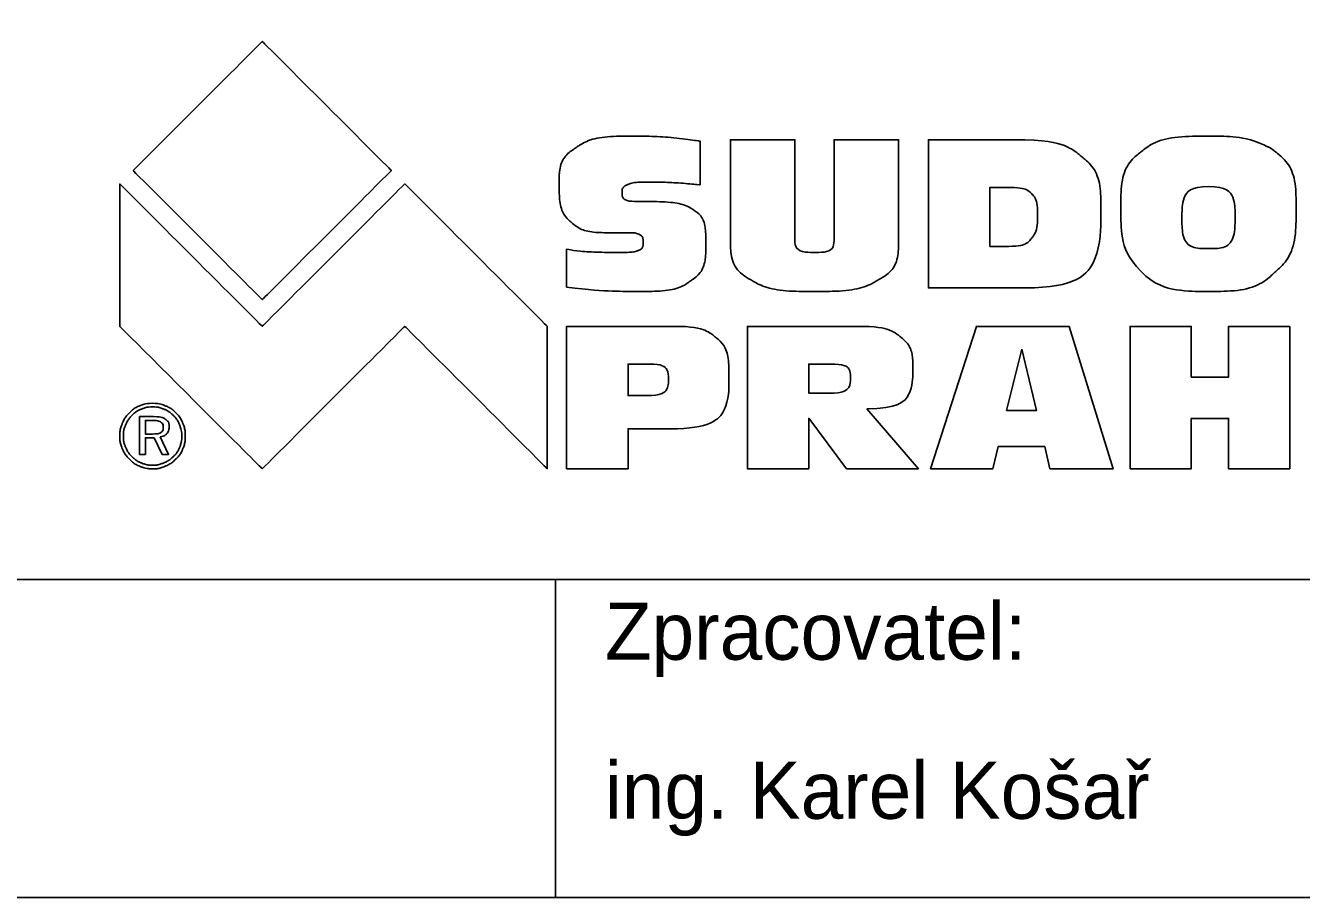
# Model space of a CAD drawing. Extents: x -311 to -101, y -2117 to -1820.
# Drawn here: x -172.5 to -130.4, y -2020.7 to -1991.91 of the extents above; entities that cross this region are included whole.
import ezdxf

# ---------------------------------------------------------------- set-up
doc = ezdxf.new("R2010")
doc.units = 0
for name, color, linetype in [('Rozpiska - logo SUDOP PRAHA', 7, 'Continuous'), ('Rozpiska_pole_6', 7, 'Continuous'), ('Rozpiska_pole_7', 7, 'Continuous')]:
    doc.layers.add(name, color=color, linetype=linetype)

msp = doc.modelspace()

# ---------------------------------------------------------------- linework, layer by layer
at = {"layer": 'Rozpiska - logo SUDOP PRAHA'}
for points in [[(-139.881, -1995.683), (-142.705, -1995.683), (-142.705, -2000.574), (-139.503, -2000.574)], [(-140.057, -1999.203), (-140.679, -1999.203), (-140.679, -1997.255), (-140.126, -1997.255)], [(-151.132, -2001.843), (-154.65, -2001.843), (-154.65, -2006.546), (-152.618, -2006.546), (-152.618, -2005.225), (-151.212, -2005.225)], [(-145.099, -2001.843), (-148.678, -2001.843), (-148.678, -2006.546), (-146.654, -2006.546), (-146.654, -2004.879), (-145.407, -2006.546), (-143.035, -2006.546), (-144.743, -2004.563)], [(-140.582, -2006.546), (-140.405, -2005.813), (-138.867, -2005.813), (-138.697, -2006.546), (-136.615, -2006.546), (-138.066, -2001.843), (-141.126, -2001.843), (-142.635, -2006.546), (-140.582, -2006.546)], [(-139.629, -2002.596), (-139.139, -2004.618), (-140.126, -2004.618), (-139.629, -2002.596)], [(-152.015, -2004.127), (-152.618, -2004.127), (-152.618, -2003.087), (-151.913, -2003.087)], [(-145.978, -2004.049), (-146.654, -2004.049), (-146.654, -2003.087), (-145.953, -2003.087)], [(-168.28, -2004.824), (-168.737, -2004.824), (-168.737, -2006.069), (-168.549, -2006.069), (-168.549, -2005.522), (-168.258, -2005.522), (-167.995, -2006.069), (-167.781, -2006.069), (-168.059, -2005.495)], [(-168.316, -2005.398), (-168.549, -2005.398), (-168.549, -2004.951), (-168.316, -2004.951)]]:
    msp.add_lwpolyline(points, dxfattribs=at)
for points in [[(-168.952, -1996.7), (-168.952, -1996.7), (-164.69, -1992.438), (-164.69, -1992.438), (-164.69, -1992.438), (-164.69, -1992.438), (-160.429, -1996.7), (-160.429, -1996.7), (-160.429, -1996.7), (-160.429, -1996.7), (-164.69, -2000.961), (-164.69, -2000.961), (-164.69, -2000.961), (-164.69, -2000.961), (-168.952, -1996.7), (-168.952, -1996.7)], [(-154.65, -2000.554), (-153.886, -2000.645), (-153.084, -2000.691), (-152.243, -2000.691), (-152.243, -2000.691), (-151.439, -2000.691), (-150.872, -2000.573), (-150.544, -2000.336), (-150.544, -2000.336), (-150.214, -2000.1), (-150.049, -1999.692), (-150.049, -1999.112), (-150.049, -1999.112), (-150.049, -1998.545), (-150.198, -1998.167), (-150.495, -1997.978), (-150.495, -1997.978), (-150.775, -1997.808), (-151.344, -1997.723), (-152.202, -1997.723), (-152.202, -1997.723), (-152.613, -1997.723), (-152.819, -1997.626), (-152.819, -1997.432), (-152.819, -1997.432), (-152.819, -1997.309), (-152.758, -1997.22), (-152.637, -1997.165), (-152.637, -1997.165), (-152.514, -1997.109), (-152.298, -1997.081), (-151.99, -1997.081), (-151.99, -1997.081), (-151.468, -1997.081), (-150.895, -1997.111), (-150.244, -1997.171), (-150.244, -1997.171), (-150.244, -1997.171), (-150.244, -1995.729), (-150.244, -1995.729), (-150.244, -1995.729), (-151.021, -1995.62), (-151.748, -1995.565), (-152.452, -1995.565), (-152.452, -1995.565), (-153.337, -1995.565), (-153.965, -1995.691), (-154.336, -1995.943), (-154.336, -1995.943), (-154.707, -1996.193), (-154.892, -1996.593), (-154.892, -1997.141), (-154.892, -1997.141), (-154.892, -1997.75), (-154.76, -1998.172), (-154.495, -1998.406), (-154.495, -1998.406), (-154.228, -1998.64), (-153.784, -1998.755), (-153.163, -1998.751), (-153.163, -1998.751), (-153.163, -1998.751), (-152.645, -1998.751), (-152.645, -1998.751), (-152.645, -1998.751), (-152.463, -1998.751), (-152.331, -1998.771), (-152.247, -1998.811), (-152.247, -1998.811), (-152.164, -1998.851), (-152.122, -1998.938), (-152.122, -1999.072), (-152.122, -1999.072), (-152.122, -1999.212), (-152.177, -1999.303), (-152.285, -1999.343), (-152.285, -1999.343), (-152.391, -1999.383), (-152.57, -1999.403), (-152.822, -1999.403), (-152.822, -1999.403), (-153.605, -1999.403), (-154.214, -1999.369), (-154.65, -1999.299), (-154.65, -1999.299), (-154.65, -1999.299), (-154.65, -2000.554), (-154.65, -2000.554)], [(-149.242, -1999.008), (-149.242, -1999.609), (-149.022, -2000.041), (-148.581, -2000.302), (-148.581, -2000.302), (-148.141, -2000.562), (-147.443, -2000.691), (-146.489, -2000.691), (-146.489, -2000.691), (-145.493, -2000.691), (-144.779, -2000.562), (-144.346, -2000.302), (-144.346, -2000.302), (-143.911, -2000.043), (-143.693, -1999.605), (-143.693, -1998.988), (-143.693, -1998.988), (-143.693, -1998.988), (-143.693, -1995.683), (-143.693, -1995.683), (-143.693, -1995.683), (-143.693, -1995.683), (-145.82, -1995.683), (-145.82, -1995.683), (-145.82, -1995.683), (-145.82, -1995.683), (-145.82, -1998.921), (-145.82, -1998.921), (-145.82, -1998.921), (-145.82, -1999.241), (-146.033, -1999.401), (-146.458, -1999.401), (-146.458, -1999.401), (-146.896, -1999.401), (-147.115, -1999.236), (-147.115, -1998.908), (-147.115, -1998.908), (-147.115, -1998.908), (-147.115, -1995.683), (-147.115, -1995.683), (-147.115, -1995.683), (-147.115, -1995.683), (-149.242, -1995.683), (-149.242, -1995.683), (-149.242, -1995.683), (-149.242, -1995.683), (-149.242, -1999.008), (-149.242, -1999.008)], [(-139.503, -2000.574), (-137.845, -2000.574), (-137.015, -1999.708), (-137.015, -1997.977), (-137.015, -1997.977), (-137.015, -1997.166), (-137.234, -1996.582), (-137.672, -1996.224), (-137.672, -1996.224), (-138.109, -1995.863), (-138.846, -1995.683), (-139.881, -1995.683)], [(-131.642, -1995.853), (-132.079, -1995.661), (-132.679, -1995.565), (-133.444, -1995.565), (-133.444, -1995.565), (-134.515, -1995.565), (-135.268, -1995.742), (-135.704, -1996.094), (-135.704, -1996.094), (-136.139, -1996.444), (-136.357, -1997.069), (-136.357, -1997.968), (-136.357, -1997.968), (-136.357, -1998.904), (-136.135, -1999.593), (-135.692, -2000.032)], [(-135.692, -2000.032), (-135.249, -2000.471), (-134.507, -2000.691), (-133.467, -2000.691), (-133.467, -2000.691), (-132.467, -2000.691), (-131.735, -2000.48), (-131.272, -2000.059), (-131.272, -2000.059), (-130.806, -1999.637), (-130.573, -1998.94), (-130.573, -1997.968), (-130.573, -1997.968), (-130.573, -1997.093), (-130.788, -1996.474), (-131.218, -1996.111), (-131.218, -1996.111), (-131.336, -1996.011), (-131.478, -1995.925), (-131.642, -1995.853)], [(-169.393, -2001.843), (-169.393, -2001.843), (-164.69, -2006.546), (-164.69, -2006.546), (-164.69, -2006.546), (-164.69, -2006.546), (-159.988, -2001.843), (-159.988, -2001.843), (-159.988, -2001.843), (-159.988, -2001.843), (-155.285, -2006.546), (-155.285, -2006.546), (-155.285, -2006.546), (-155.285, -2006.546), (-155.285, -2001.843), (-155.285, -2001.843), (-155.285, -2001.843), (-155.285, -2001.843), (-159.988, -1997.14), (-159.988, -1997.14), (-159.988, -1997.14), (-159.988, -1997.14), (-164.69, -2001.843), (-164.69, -2001.843), (-164.69, -2001.843), (-164.69, -2001.843), (-169.393, -1997.14), (-169.393, -1997.14), (-169.393, -1997.14), (-169.393, -1997.14), (-169.393, -2001.843), (-169.393, -2001.843)], [(-140.126, -1997.255), (-139.711, -1997.255), (-139.437, -1997.324), (-139.305, -1997.463), (-139.305, -1997.463), (-139.173, -1997.6), (-139.107, -1997.833), (-139.107, -1998.162), (-139.107, -1998.162), (-139.107, -1998.518), (-139.175, -1998.781), (-139.313, -1998.951), (-139.313, -1998.951), (-139.448, -1999.119), (-139.696, -1999.203), (-140.057, -1999.203)], [(-133.459, -1997.231), (-132.879, -1997.231), (-132.589, -1997.556), (-132.589, -1998.205), (-132.589, -1998.205), (-132.589, -1998.919), (-132.879, -1999.276), (-133.459, -1999.276), (-133.459, -1999.276), (-134.047, -1999.276), (-134.34, -1998.936), (-134.34, -1998.255), (-134.34, -1998.255), (-134.34, -1997.573), (-134.047, -1997.231), (-133.459, -1997.231)], [(-151.212, -2005.225), (-149.93, -2005.225), (-149.289, -2004.648), (-149.289, -2003.494), (-149.289, -2003.494), (-149.289, -2002.876), (-149.436, -2002.446), (-149.731, -2002.205), (-149.731, -2002.205), (-150.023, -2001.964), (-150.49, -2001.843), (-151.132, -2001.843)], [(-144.743, -2004.563), (-143.73, -2004.563), (-143.224, -2004.12), (-143.224, -2003.235), (-143.224, -2003.235), (-143.224, -2002.751), (-143.367, -2002.398), (-143.652, -2002.176), (-143.652, -2002.176), (-143.938, -2001.954), (-144.42, -2001.843), (-145.099, -2001.843)], [(-136.051, -2006.546), (-136.051, -2006.546), (-134.032, -2006.546), (-134.032, -2006.546), (-134.032, -2006.546), (-134.032, -2006.546), (-134.032, -2004.882), (-134.032, -2004.882), (-134.032, -2004.882), (-134.032, -2004.882), (-132.803, -2004.882), (-132.803, -2004.882), (-132.803, -2004.882), (-132.803, -2004.882), (-132.803, -2006.546), (-132.803, -2006.546), (-132.803, -2006.546), (-132.803, -2006.546), (-130.784, -2006.546), (-130.784, -2006.546), (-130.784, -2006.546), (-130.784, -2006.546), (-130.784, -2001.843), (-130.784, -2001.843), (-130.784, -2001.843), (-130.784, -2001.843), (-132.803, -2001.843), (-132.803, -2001.843), (-132.803, -2001.843), (-132.803, -2001.843), (-132.803, -2003.516), (-132.803, -2003.516), (-132.803, -2003.516), (-132.803, -2003.516), (-134.032, -2003.516), (-134.032, -2003.516), (-134.032, -2003.516), (-134.032, -2003.516), (-134.032, -2001.843), (-134.032, -2001.843), (-134.032, -2001.843), (-134.032, -2001.843), (-136.051, -2001.843), (-136.051, -2001.843), (-136.051, -2001.843), (-136.051, -2001.843), (-136.051, -2006.546), (-136.051, -2006.546)], [(-151.913, -2003.087), (-151.497, -2003.087), (-151.289, -2003.257), (-151.289, -2003.597), (-151.289, -2003.597), (-151.289, -2003.95), (-151.531, -2004.127), (-152.015, -2004.127)], [(-145.953, -2003.087), (-145.504, -2003.087), (-145.28, -2003.234), (-145.28, -2003.529), (-145.28, -2003.529), (-145.28, -2003.876), (-145.513, -2004.049), (-145.978, -2004.049)], [(-168.313, -2004.383), (-168.459, -2004.383), (-168.598, -2004.409), (-168.727, -2004.462), (-168.727, -2004.462), (-168.856, -2004.516), (-168.97, -2004.593), (-169.069, -2004.694), (-169.069, -2004.694), (-169.174, -2004.799), (-169.254, -2004.918), (-169.309, -2005.052), (-169.309, -2005.052), (-169.365, -2005.185), (-169.393, -2005.322), (-169.393, -2005.464), (-169.393, -2005.464), (-169.393, -2005.608), (-169.366, -2005.745), (-169.312, -2005.876), (-169.312, -2005.876), (-169.257, -2006.007), (-169.179, -2006.123), (-169.075, -2006.225), (-169.075, -2006.225), (-168.973, -2006.33), (-168.856, -2006.409), (-168.726, -2006.464), (-168.726, -2006.464), (-168.667, -2006.489), (-168.606, -2006.508), (-168.544, -2006.521)], [(-167.348, -2005.468), (-167.348, -2005.602), (-167.371, -2005.724), (-167.418, -2005.838), (-167.418, -2005.838), (-167.465, -2005.951), (-167.533, -2006.052), (-167.623, -2006.139), (-167.623, -2006.139), (-167.718, -2006.232), (-167.824, -2006.302), (-167.942, -2006.351), (-167.942, -2006.351), (-168.062, -2006.4), (-168.185, -2006.425), (-168.313, -2006.425), (-168.313, -2006.425), (-168.44, -2006.425), (-168.562, -2006.401), (-168.678, -2006.352), (-168.678, -2006.352), (-168.794, -2006.304), (-168.899, -2006.234), (-168.991, -2006.142), (-168.991, -2006.142), (-169.083, -2006.05), (-169.153, -2005.946), (-169.202, -2005.83), (-169.202, -2005.83), (-169.251, -2005.714), (-169.275, -2005.592), (-169.275, -2005.466), (-169.275, -2005.466), (-169.275, -2005.339), (-169.25, -2005.217), (-169.2, -2005.099), (-169.2, -2005.099), (-169.15, -2004.982), (-169.079, -2004.876), (-168.986, -2004.78), (-168.986, -2004.78), (-168.895, -2004.69), (-168.792, -2004.621), (-168.677, -2004.574), (-168.677, -2004.574), (-168.562, -2004.527), (-168.441, -2004.503), (-168.313, -2004.503), (-168.313, -2004.503), (-168.181, -2004.503), (-168.056, -2004.527), (-167.938, -2004.577), (-167.938, -2004.577), (-167.82, -2004.625), (-167.716, -2004.695), (-167.623, -2004.786), (-167.623, -2004.786), (-167.534, -2004.876), (-167.466, -2004.979), (-167.419, -2005.096), (-167.419, -2005.096), (-167.372, -2005.213), (-167.348, -2005.337), (-167.348, -2005.468)], [(-168.544, -2006.521), (-168.469, -2006.538), (-168.392, -2006.546), (-168.313, -2006.546), (-168.313, -2006.546), (-168.17, -2006.546), (-168.032, -2006.518), (-167.899, -2006.462), (-167.899, -2006.462), (-167.766, -2006.407), (-167.647, -2006.327), (-167.542, -2006.222), (-167.542, -2006.222), (-167.439, -2006.122), (-167.361, -2006.008), (-167.309, -2005.879), (-167.309, -2005.879), (-167.256, -2005.75), (-167.23, -2005.611), (-167.23, -2005.464), (-167.23, -2005.464), (-167.23, -2005.317), (-167.256, -2005.179), (-167.311, -2005.047), (-167.311, -2005.047), (-167.364, -2004.916), (-167.441, -2004.8), (-167.542, -2004.7), (-167.542, -2004.7), (-167.643, -2004.597), (-167.759, -2004.518), (-167.891, -2004.464), (-167.891, -2004.464), (-168.023, -2004.41), (-168.163, -2004.383), (-168.313, -2004.383)], [(-168.316, -2004.951), (-168.19, -2004.951), (-168.099, -2004.969), (-168.043, -2005.005), (-168.043, -2005.005), (-167.987, -2005.04), (-167.959, -2005.099), (-167.959, -2005.181), (-167.959, -2005.181), (-167.959, -2005.259), (-167.985, -2005.315), (-168.038, -2005.349), (-168.038, -2005.349), (-168.091, -2005.381), (-168.184, -2005.398), (-168.316, -2005.398)], [(-168.059, -2005.495), (-167.969, -2005.483), (-167.898, -2005.447), (-167.845, -2005.388), (-167.845, -2005.388), (-167.792, -2005.328), (-167.765, -2005.255), (-167.765, -2005.168), (-167.765, -2005.168), (-167.765, -2005.05), (-167.807, -2004.964), (-167.891, -2004.908), (-167.891, -2004.908), (-167.975, -2004.852), (-168.105, -2004.824), (-168.28, -2004.824)]]:
    msp.add_open_spline(points, degree=3, dxfattribs=at)
at = {"layer": 'Rozpiska_pole_6'}
msp.add_lwpolyline([(-291.878, -1968.197), (-113.378, -1968.197), (-113.378, -2020.697), (-291.878, -2020.697)], close=True, dxfattribs=at)
at = {"layer": 'Rozpiska_pole_7'}
for p, q in [((-291.878, -2010.197), (-113.378, -2010.197)), ((-155.011, -2020.697), (-155.011, -2010.197))]:
    msp.add_line(p, q, dxfattribs=at)

# ---------------------------------------------------------------- texts
at = {"layer": 'Rozpiska_pole_6'}
for s, p in [('Zpracovatel:', (-153.387, -2012.85)), ('ing. Karel Košař', (-153.387, -2018.1))]:
    msp.add_text(s, height=1.89, dxfattribs=at).set_placement(p)

doc.saveas('drawing.dxf')
